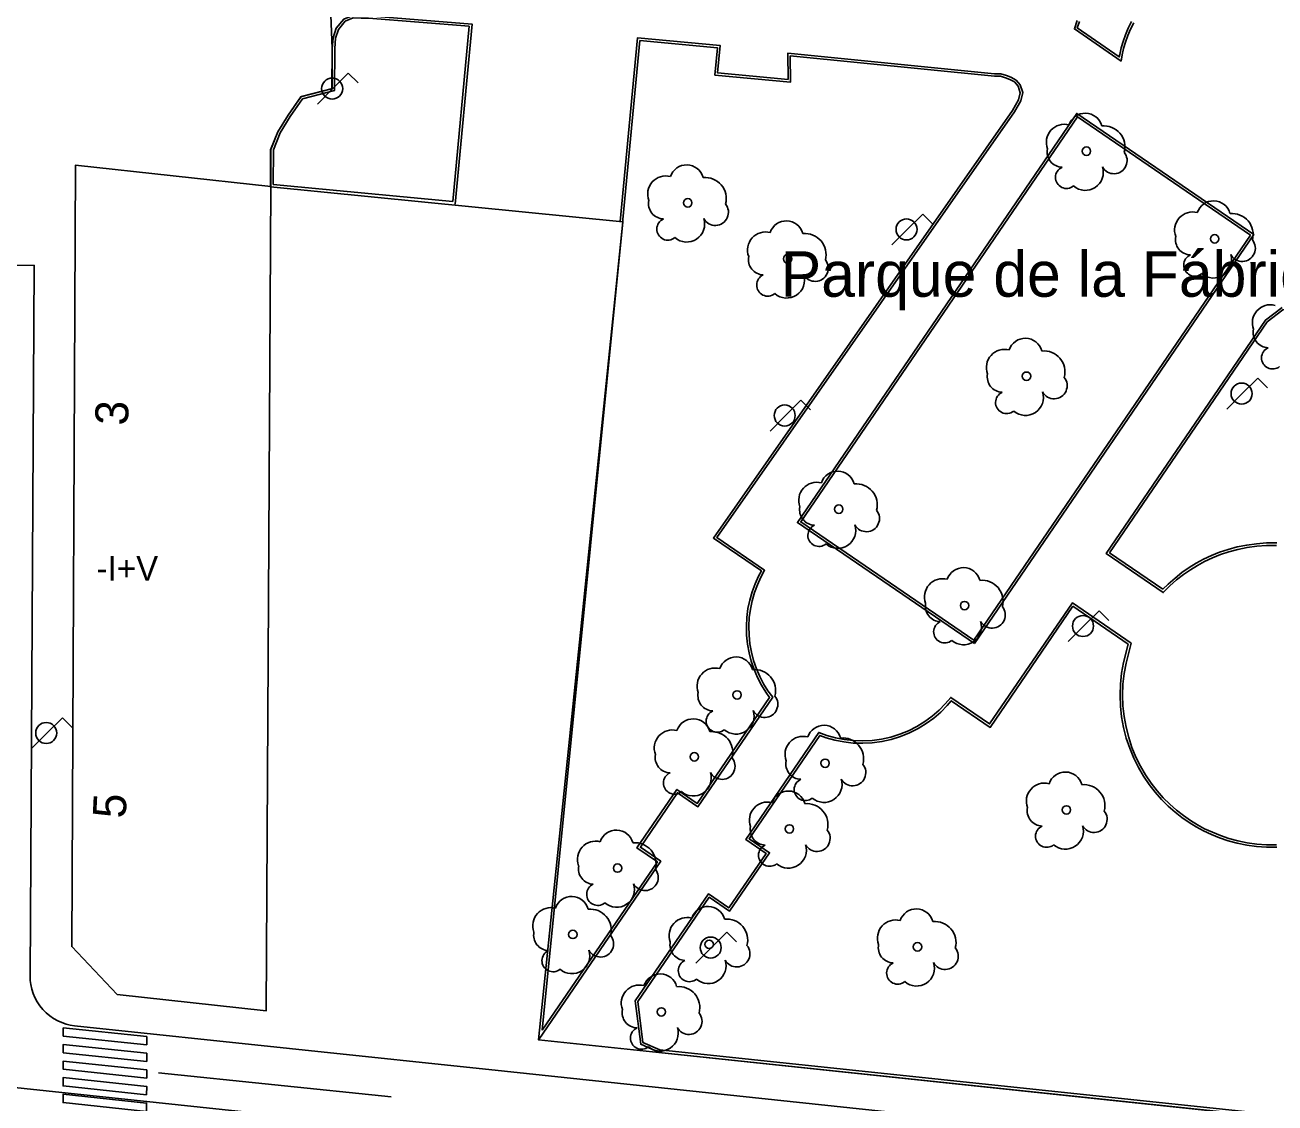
# Model space of a CAD drawing. Extents: x 282771 to 285132, y 4823109 to 4825496.
# Drawn here: x 282862 to 282937.8, y 4824029.5 to 4824094.8 of the extents above; entities that cross this region are included whole.
import ezdxf

# ---------------------------------------------------------------- set-up
doc = ezdxf.new("R2010")
doc.units = 0
for name, color, linetype in [('ACERA-BORDILLO', 7, 'Continuous'), ('ARBOL', 7, 'Continuous'), ('BORDILLO', 7, 'Continuous'), ('CALLE-EJE', 7, 'Continuous'), ('EDIFICIO', 7, 'Continuous'), ('FAROLA', 7, 'Continuous'), ('NUM-PORTAL', 7, 'Continuous'), ('PARQUE-JARDIN-AREA', 7, 'Continuous'), ('PARQUE-JARDIN-TEXTO', 7, 'Continuous'), ('PASO-PEATONES', 7, 'Continuous'), ('SENAL-VIARIA', 7, 'Continuous'), ('TXT-ALTURA-EDIFICIO', 7, 'Continuous'), ('ZONA-VERDE', 7, 'Continuous')]:
    doc.layers.add(name, color=color, linetype=linetype)

msp = doc.modelspace()

# ---------------------------------------------------------------- linework, layer by layer
at = {"layer": 'ACERA-BORDILLO'}
for points in [[(282988.023, 4824157.68), (282986.043, 4824139.146), (282981.145, 4824135.33), (282970.859, 4824041.966), (282974.673, 4824036.985), (282973.917, 4824027.481), (282973.629, 4824024.412), (282973.445, 4824023.861), (282973.196, 4824023.428), (282972.724, 4824023.074), (282972.2, 4824022.851), (282971.518, 4824022.891), (282891.09, 4824031.424)], [(282891.09, 4824031.424), (282865.031, 4824034.178), (282864.778, 4824034.216), (282864.522, 4824034.277), (282864.266, 4824034.363), (282864.014, 4824034.474), (282863.768, 4824034.61), (282863.534, 4824034.771), (282863.313, 4824034.956), (282863.111, 4824035.162), (282862.929, 4824035.386), (282862.77, 4824035.625), (282862.636, 4824035.876), (282862.527, 4824036.135), (282862.445, 4824036.399), (282862.388, 4824036.663), (282862.356, 4824036.924), (282862.346, 4824037.179), (282862.594, 4824080.223), (282861.132, 4824080.231), (282861.242, 4824099.318), (282862.704, 4824099.31)]]:
    msp.add_lwpolyline(points, dxfattribs=at)
at = {"layer": 'ARBOL'}
for centre in [(282926.33, 4824087.143), (282902.18, 4824084.013), (282934.1, 4824081.833), (282908.23, 4824080.623), (282922.7, 4824073.513), (282911.33, 4824065.463), (282918.95, 4824059.623), (282905.17, 4824054.213), (282902.58, 4824050.463), (282910.5, 4824050.073), (282925.12, 4824047.244), (282908.34, 4824046.094), (282897.93, 4824043.724), (282895.22, 4824039.704), (282903.48, 4824039.104), (282916.1, 4824038.954), (282900.58, 4824035.014)]:
    msp.add_circle(centre, 0.255, dxfattribs=at)
for centre, radius, start, end in [((282926.26, 4824088.403), 1.038, 15.64228, 161.38435), ((282925, 4824087.673), 1.097, 75.4318, 200.55608), ((282927.39, 4824087.403), 1.272, 345.03273, 95.79925), ((282924.89, 4824087.103), 0.935, 168.59898, 268.13236), ((282928, 4824086.573), 0.797, 208.96247, 38.99103), ((282900.85, 4824084.543), 1.097, 75.4318, 200.55608), ((282902.11, 4824085.273), 1.038, 15.64228, 161.38435), ((282925.13, 4824085.553), 0.672, 113.73672, 309.4725), ((282926.27, 4824085.853), 1.086, 228.95447, 17.92796), ((282903.24, 4824084.273), 1.272, 345.03273, 95.79925), ((282900.74, 4824083.973), 0.935, 168.59898, 268.13236), ((282934.03, 4824083.093), 1.038, 15.64228, 161.38435), ((282903.85, 4824083.443), 0.797, 208.96247, 38.99103), ((282932.77, 4824082.363), 1.097, 75.4318, 200.55608), ((282935.16, 4824082.093), 1.272, 345.03273, 95.79925), ((282900.98, 4824082.423), 0.672, 113.73672, 309.4725), ((282902.12, 4824082.723), 1.086, 228.95447, 17.92796), ((282908.16, 4824081.883), 1.038, 15.64228, 161.38435), ((282906.9, 4824081.153), 1.097, 75.4318, 200.55608), ((282909.29, 4824080.883), 1.272, 345.03273, 95.79925), ((282932.66, 4824081.793), 0.935, 168.59898, 268.13236), ((282935.77, 4824081.263), 0.797, 208.96247, 38.99103), ((282906.79, 4824080.583), 0.935, 168.59898, 268.13236), ((282909.9, 4824080.053), 0.797, 208.96247, 38.99103), ((282932.9, 4824080.243), 0.672, 113.73672, 309.4725), ((282934.04, 4824080.543), 1.086, 228.95447, 17.92796), ((282907.03, 4824079.033), 0.672, 113.73672, 309.4725), ((282908.17, 4824079.333), 1.086, 228.95447, 17.92796), ((282937.48, 4824076.743), 1.097, 75.4318, 200.55608), ((282922.63, 4824074.773), 1.038, 15.64228, 161.38435), ((282937.37, 4824076.173), 0.935, 168.59898, 268.13236), ((282921.37, 4824074.043), 1.097, 75.4318, 200.55608), ((282923.76, 4824073.773), 1.272, 345.03273, 95.79925), ((282937.61, 4824074.623), 0.672, 113.73672, 309.4725), ((282921.26, 4824073.473), 0.935, 168.59898, 268.13236), ((282924.37, 4824072.943), 0.797, 208.96247, 38.99103), ((282921.5, 4824071.923), 0.672, 113.73672, 309.4725), ((282922.64, 4824072.223), 1.086, 228.95447, 17.92796), ((282911.26, 4824066.723), 1.038, 15.64228, 161.38435), ((282910, 4824065.993), 1.097, 75.4318, 200.55608), ((282912.39, 4824065.723), 1.272, 345.03273, 95.79925), ((282909.89, 4824065.423), 0.935, 168.59898, 268.13236), ((282913, 4824064.893), 0.797, 208.96247, 38.99103), ((282910.13, 4824063.873), 0.672, 113.73672, 309.4725), ((282911.27, 4824064.173), 1.086, 228.95447, 17.92796), ((282918.88, 4824060.883), 1.038, 15.64228, 161.38435), ((282917.62, 4824060.153), 1.097, 75.4318, 200.55608), ((282920.01, 4824059.883), 1.272, 345.03273, 95.79925), ((282917.51, 4824059.583), 0.935, 168.59898, 268.13236), ((282920.62, 4824059.053), 0.797, 208.96247, 38.99103), ((282917.75, 4824058.033), 0.672, 113.73672, 309.4725), ((282918.89, 4824058.333), 1.086, 228.95447, 17.92796), ((282905.1, 4824055.473), 1.038, 15.64228, 161.38435), ((282903.84, 4824054.743), 1.097, 75.4318, 200.55608), ((282906.23, 4824054.473), 1.272, 345.03273, 95.79925), ((282903.73, 4824054.173), 0.935, 168.59898, 268.13236), ((282906.84, 4824053.643), 0.797, 208.96247, 38.99103), ((282903.97, 4824052.623), 0.672, 113.73672, 309.4725), ((282905.11, 4824052.923), 1.086, 228.95447, 17.92796), ((282902.51, 4824051.723), 1.038, 15.64228, 161.38435), ((282910.43, 4824051.333), 1.038, 15.64228, 161.38435), ((282901.25, 4824050.993), 1.097, 75.4318, 200.55608), ((282903.64, 4824050.723), 1.272, 345.03273, 95.79925), ((282909.17, 4824050.603), 1.097, 75.4318, 200.55608), ((282911.56, 4824050.333), 1.272, 345.03273, 95.79925), ((282901.14, 4824050.423), 0.935, 168.59898, 268.13236), ((282904.25, 4824049.893), 0.797, 208.96247, 38.99103), ((282909.06, 4824050.033), 0.935, 168.59898, 268.13236), ((282901.38, 4824048.873), 0.672, 113.73672, 309.4725), ((282902.52, 4824049.173), 1.086, 228.95447, 17.92796), ((282912.17, 4824049.503), 0.797, 208.96247, 38.99103), ((282925.05, 4824048.504), 1.038, 15.64228, 161.38435), ((282909.3, 4824048.484), 0.672, 113.73672, 309.4725), ((282910.44, 4824048.784), 1.086, 228.95447, 17.92796), ((282923.79, 4824047.774), 1.097, 75.4318, 200.55608), ((282926.18, 4824047.504), 1.272, 345.03273, 95.79925), ((282908.27, 4824047.354), 1.038, 15.64228, 161.38435), ((282907.01, 4824046.624), 1.097, 75.4318, 200.55608), ((282909.4, 4824046.354), 1.272, 345.03273, 95.79925), ((282923.68, 4824047.204), 0.935, 168.59898, 268.13236), ((282926.79, 4824046.674), 0.797, 208.96247, 38.99103), ((282906.9, 4824046.054), 0.935, 168.59898, 268.13236), ((282923.92, 4824045.654), 0.672, 113.73672, 309.4725), ((282925.06, 4824045.954), 1.086, 228.95447, 17.92796), ((282897.86, 4824044.984), 1.038, 15.64228, 161.38435), ((282910.01, 4824045.524), 0.797, 208.96247, 38.99103), ((282896.6, 4824044.254), 1.097, 75.4318, 200.55608), ((282898.99, 4824043.984), 1.272, 345.03273, 95.79925), ((282907.14, 4824044.504), 0.672, 113.73672, 309.4725), ((282908.28, 4824044.804), 1.086, 228.95447, 17.92796), ((282896.49, 4824043.684), 0.935, 168.59898, 268.13236), ((282899.6, 4824043.154), 0.797, 208.96247, 38.99103), ((282896.73, 4824042.134), 0.672, 113.73672, 309.4725), ((282897.87, 4824042.434), 1.086, 228.95447, 17.92796), ((282895.15, 4824040.964), 1.038, 15.64228, 161.38435), ((282893.89, 4824040.234), 1.097, 75.4318, 200.55608), ((282896.28, 4824039.964), 1.272, 345.03273, 95.79925), ((282903.41, 4824040.364), 1.038, 15.64228, 161.38435), ((282916.03, 4824040.214), 1.038, 15.64228, 161.38435), ((282902.15, 4824039.634), 1.097, 75.4318, 200.55608), ((282904.54, 4824039.364), 1.272, 345.03273, 95.79925), ((282914.77, 4824039.484), 1.097, 75.4318, 200.55608), ((282917.16, 4824039.214), 1.272, 345.03273, 95.79925), ((282893.78, 4824039.664), 0.935, 168.59898, 268.13236), ((282896.89, 4824039.134), 0.797, 208.96247, 38.99103), ((282894.02, 4824038.114), 0.672, 113.73672, 309.4725), ((282895.16, 4824038.414), 1.086, 228.95447, 17.92796), ((282902.04, 4824039.064), 0.935, 168.59898, 268.13236), ((282905.15, 4824038.534), 0.797, 208.96247, 38.99103), ((282914.66, 4824038.914), 0.935, 168.59898, 268.13236), ((282917.77, 4824038.384), 0.797, 208.96247, 38.99103), ((282902.28, 4824037.514), 0.672, 113.73672, 309.4725), ((282903.42, 4824037.814), 1.086, 228.95447, 17.92796), ((282914.9, 4824037.364), 0.672, 113.73672, 309.4725), ((282916.04, 4824037.664), 1.086, 228.95447, 17.92796), ((282900.51, 4824036.274), 1.038, 15.64228, 161.38435), ((282899.25, 4824035.544), 1.097, 75.4318, 200.55608), ((282901.64, 4824035.274), 1.272, 345.03273, 95.79925), ((282899.14, 4824034.974), 0.935, 168.59898, 268.13236), ((282902.25, 4824034.444), 0.797, 208.96247, 38.99103), ((282899.38, 4824033.424), 0.672, 113.73672, 309.4725), ((282900.52, 4824033.724), 1.086, 228.95447, 17.92796)]:
    msp.add_arc(centre, radius, start, end, dxfattribs=at)
at = {"layer": 'BORDILLO'}
for points in [[(282888.082, 4824083.938), (282889.113, 4824094.841), (282882.85, 4824095.343), (282882.408, 4824095.342), (282881.892, 4824095.369), (282881.341, 4824095.14), (282880.883, 4824094.589), (282880.699, 4824094.015), (282880.648, 4824093.367), (282880.64, 4824090.933), (282878.762, 4824090.447), (282877.969, 4824089.333), (282877.349, 4824088.323), (282876.93, 4824087.243), (282876.92, 4824084.993)], [(282929.195, 4824094.921), (282929.002, 4824094.531), (282928.837, 4824094.139), (282928.699, 4824093.747), (282928.586, 4824093.358), (282928.498, 4824092.975), (282928.433, 4824092.598), (282925.601, 4824094.546), (282925.766, 4824095.047)], [(282893.16, 4824033.334), (282900.55, 4824044.134), (282899.31, 4824044.984), (282901.56, 4824048.284), (282902.8, 4824047.434), (282907.327, 4824054.065), (282907.041, 4824054.459), (282906.78, 4824054.882), (282906.546, 4824055.329), (282906.343, 4824055.8), (282906.174, 4824056.29), (282906.042, 4824056.796), (282905.948, 4824057.314), (282905.895, 4824057.839), (282905.882, 4824058.367), (282905.91, 4824058.892), (282905.977, 4824059.411), (282906.083, 4824059.918), (282906.225, 4824060.411), (282906.4, 4824060.884), (282906.607, 4824061.336), (282906.84, 4824061.763), (282903.95, 4824063.743), (282921.978, 4824089.518), (282922.365, 4824090.193), (282922.483, 4824090.692), (282922.325, 4824091.151), (282922.076, 4824091.452), (282921.762, 4824091.623), (282921.486, 4824091.728), (282921.146, 4824091.833), (282920.762, 4824091.836), (282908.235, 4824093.075), (282908.258, 4824091.492), (282903.991, 4824091.882), (282904.151, 4824093.534), (282899.145, 4824094.013), (282898.092, 4824082.876)], [(282919.55, 4824057.323), (282908.82, 4824064.653), (282925.75, 4824089.433), (282936.48, 4824082.093), (282919.55, 4824057.323)], [(282938.181, 4824077.674), (282937.178, 4824076.911), (282927.524, 4824062.778), (282930.983, 4824060.413), (282931.386, 4824060.816), (282931.794, 4824061.176), (282932.21, 4824061.502), (282932.632, 4824061.795), (282933.057, 4824062.056), (282933.495, 4824062.294), (282933.96, 4824062.513), (282934.451, 4824062.71), (282934.966, 4824062.883), (282935.505, 4824063.028), (282936.066, 4824063.142), (282936.646, 4824063.222), (282937.243, 4824063.265), (282937.853, 4824063.268)], [(282929.042, 4824057.35), (282925.479, 4824059.786), (282920.47, 4824052.453), (282918.116, 4824054.062), (282917.779, 4824053.662), (282917.403, 4824053.281), (282916.99, 4824052.924), (282916.542, 4824052.595), (282916.063, 4824052.3), (282915.555, 4824052.043), (282915.024, 4824051.828), (282914.475, 4824051.657), (282913.913, 4824051.534), (282913.345, 4824051.458), (282912.777, 4824051.429), (282912.214, 4824051.448), (282911.662, 4824051.512), (282911.127, 4824051.618), (282910.611, 4824051.763), (282910.12, 4824051.943), (282905.69, 4824045.464), (282906.93, 4824044.614), (282904.67, 4824041.314), (282903.44, 4824042.164), (282899.006, 4824035.679), (282899.331, 4824033.054), (282900.447, 4824032.562), (282957.582, 4824026.536)], [(282937.853, 4824045.134), (282937.243, 4824045.137), (282936.646, 4824045.18), (282936.066, 4824045.26), (282935.505, 4824045.374), (282934.966, 4824045.519), (282934.451, 4824045.692), (282933.96, 4824045.889), (282933.495, 4824046.108), (282933.057, 4824046.346), (282932.632, 4824046.607), (282932.21, 4824046.9), (282931.794, 4824047.226), (282931.386, 4824047.586), (282930.991, 4824047.98), (282930.612, 4824048.409), (282930.252, 4824048.872), (282929.917, 4824049.367), (282929.61, 4824049.894), (282929.334, 4824050.449), (282929.093, 4824051.031), (282928.892, 4824051.636), (282928.732, 4824052.26), (282928.616, 4824052.899), (282928.545, 4824053.547), (282928.522, 4824054.201), (282928.545, 4824054.855), (282928.616, 4824055.503), (282928.732, 4824056.142), (282929.042, 4824057.35)]]:
    msp.add_lwpolyline(points, dxfattribs=at)
at = {"layer": 'CALLE-EJE'}
msp.add_lwpolyline([(282977.366, 4824018.14), (282859.299, 4824030.65)], dxfattribs=at)
at = {"layer": 'EDIFICIO'}
msp.add_lwpolyline([(282876.92, 4824084.993), (282876.641, 4824035.074), (282867.621, 4824036.064), (282864.861, 4824038.964), (282865.091, 4824086.293), (282876.92, 4824084.993)], dxfattribs=at)
at = {"layer": 'FAROLA'}
for p, q in [((282881.62, 4824091.863), (282880.68, 4824090.933)), ((282882.21, 4824091.273), (282881.62, 4824091.863)), ((282880.68, 4824090.933), (282879.75, 4824089.993)), ((282916.414, 4824083.333), (282915.474, 4824082.403)), ((282917.004, 4824082.743), (282916.414, 4824083.333)), ((282915.474, 4824082.403), (282914.544, 4824081.463)), ((282936.714, 4824073.391), (282935.774, 4824072.461)), ((282937.304, 4824072.801), (282936.714, 4824073.391)), ((282909.034, 4824072.063), (282908.094, 4824071.133)), ((282909.624, 4824071.473), (282909.034, 4824072.063)), ((282935.774, 4824072.461), (282934.844, 4824071.521)), ((282908.094, 4824071.133), (282907.165, 4824070.193)), ((282927.104, 4824059.313), (282926.164, 4824058.383)), ((282927.694, 4824058.723), (282927.104, 4824059.313)), ((282926.164, 4824058.383), (282925.234, 4824057.443)), ((282864.299, 4824052.833), (282863.359, 4824051.903)), ((282864.889, 4824052.243), (282864.299, 4824052.833)), ((282863.359, 4824051.903), (282862.429, 4824050.964)), ((282904.551, 4824039.84), (282903.611, 4824038.91)), ((282905.141, 4824039.25), (282904.551, 4824039.84)), ((282903.611, 4824038.91), (282902.681, 4824037.97))]:
    msp.add_line(p, q, dxfattribs=at)
for centre in [(282880.64, 4824090.933), (282915.434, 4824082.403), (282935.734, 4824072.461), (282908.054, 4824071.133), (282926.124, 4824058.383), (282863.319, 4824051.903), (282903.571, 4824038.91)]:
    msp.add_circle(centre, 0.637, dxfattribs=at)
at = {"layer": 'PARQUE-JARDIN-AREA'}
msp.add_lwpolyline([(282957.565, 4824026.52), (282900.429, 4824032.546), (282893.142, 4824033.318), (282898.242, 4824082.861), (282876.902, 4824084.978), (282876.912, 4824087.228), (282877.349, 4824088.323), (282877.969, 4824089.333), (282878.744, 4824090.432), (282880.622, 4824090.919), (282880.648, 4824093.367), (282880.369, 4824099.917), (282880.422, 4824101.837), (282917.293, 4824120.266), (282923.323, 4824123.277), (282968.997, 4824145.941)], dxfattribs=at)
at = {"layer": 'PASO-PEATONES'}
for points in [[(282869.41, 4824033.011), (282864.351, 4824033.546), (282864.352, 4824034.048), (282869.411, 4824033.514)], [(282869.407, 4824032.006), (282864.349, 4824032.54), (282864.35, 4824033.043), (282869.408, 4824032.509)], [(282869.405, 4824031.001), (282864.346, 4824031.535), (282864.348, 4824032.038), (282869.406, 4824031.503)], [(282869.402, 4824029.996), (282864.344, 4824030.53), (282864.345, 4824031.032), (282869.404, 4824030.498)], [(282869.4, 4824028.99), (282864.342, 4824029.524), (282864.343, 4824030.027), (282869.401, 4824029.493)]]:
    msp.add_lwpolyline(points, close=True, dxfattribs=at)
at = {"layer": 'SENAL-VIARIA'}
msp.add_lwpolyline([(282870.123, 4824031.314), (282884.225, 4824029.86)], dxfattribs=at)
at = {"layer": 'ZONA-VERDE'}
for p, q in [((282887.946, 4824084.101), (282888.949, 4824094.704)), ((282899.281, 4824093.849), (282898.255, 4824083.008)), ((282877.071, 4824085.13), (282887.946, 4824084.101)), ((282927.733, 4824062.817), (282930.965, 4824060.607)), ((282930.965, 4824060.607), (282931.283, 4824060.925)), ((282928.87, 4824057.286), (282925.518, 4824059.578))]:
    msp.add_line(p, q, dxfattribs=at)
for points in [[(282888.949, 4824094.704), (282882.845, 4824095.193), (282882.404, 4824095.192), (282881.918, 4824095.218), (282881.433, 4824095.015), (282881.017, 4824094.515), (282880.847, 4824093.986), (282880.798, 4824093.361), (282880.79, 4824090.817), (282878.852, 4824090.315), (282878.094, 4824089.25), (282877.484, 4824088.256), (282877.08, 4824087.215), (282877.071, 4824085.13)], [(282925.907, 4824094.996), (282925.779, 4824094.606), (282928.325, 4824092.854), (282928.351, 4824093.004), (282928.441, 4824093.396), (282928.556, 4824093.793), (282928.697, 4824094.193), (282928.866, 4824094.593), (282929.063, 4824094.992)], [(282893.368, 4824033.902), (282900.342, 4824044.095), (282899.102, 4824044.944), (282901.521, 4824048.492), (282902.761, 4824047.642), (282907.143, 4824054.062), (282906.916, 4824054.376), (282906.649, 4824054.807), (282906.41, 4824055.265), (282906.203, 4824055.746), (282906.03, 4824056.247), (282905.895, 4824056.764), (282905.8, 4824057.293), (282905.745, 4824057.83), (282905.732, 4824058.369), (282905.76, 4824058.906), (282905.829, 4824059.436), (282905.937, 4824059.954), (282906.082, 4824060.457), (282906.262, 4824060.941), (282906.472, 4824061.403), (282906.644, 4824061.716), (282903.74, 4824063.705), (282921.851, 4824089.598), (282922.224, 4824090.249), (282922.327, 4824090.684), (282922.192, 4824091.076), (282921.979, 4824091.334), (282921.699, 4824091.486), (282921.438, 4824091.586), (282921.122, 4824091.683), (282920.754, 4824091.686), (282908.388, 4824092.91), (282908.41, 4824091.327), (282903.827, 4824091.746), (282903.987, 4824093.399), (282899.281, 4824093.849)], [(282936.271, 4824082.054), (282925.789, 4824089.225), (282909.029, 4824064.693), (282919.511, 4824057.532), (282936.271, 4824082.054)], [(282898.255, 4824083.008), (282898.256, 4824083.008), (282898.242, 4824082.861), (282893.368, 4824033.902)], [(282945.243, 4824059.368), (282946.504, 4824059.987), (282947.471, 4824062.322), (282947.4, 4824062.491), (282944.881, 4824067.643), (282943.531, 4824066.983), (282941.639, 4824070.842), (282942.989, 4824071.502), (282940.504, 4824076.579), (282939.883, 4824077.28), (282939.197, 4824077.544), (282938.233, 4824077.525), (282937.288, 4824076.806), (282927.733, 4824062.817)], [(282931.283, 4824060.925), (282931.698, 4824061.291), (282932.121, 4824061.623), (282932.55, 4824061.921), (282932.982, 4824062.186), (282933.428, 4824062.427), (282933.9, 4824062.65), (282934.399, 4824062.851), (282934.923, 4824063.027), (282935.471, 4824063.174), (282936.041, 4824063.29), (282936.631, 4824063.371), (282937.237, 4824063.415), (282937.857, 4824063.418)], [(282925.518, 4824059.578), (282920.509, 4824052.245), (282918.143, 4824053.862), (282917.89, 4824053.561), (282917.506, 4824053.171), (282917.084, 4824052.806), (282916.626, 4824052.47), (282916.136, 4824052.169), (282915.617, 4824051.906), (282915.074, 4824051.687), (282914.513, 4824051.512), (282913.939, 4824051.386), (282913.359, 4824051.308), (282912.778, 4824051.279), (282912.203, 4824051.298), (282911.639, 4824051.364), (282911.092, 4824051.472), (282910.565, 4824051.62), (282910.178, 4824051.762), (282905.899, 4824045.503), (282907.139, 4824044.652), (282904.709, 4824041.105), (282903.479, 4824041.954), (282899.162, 4824035.642), (282899.47, 4824033.157), (282900.487, 4824032.709), (282957.555, 4824026.69)], [(282937.857, 4824044.984), (282937.237, 4824044.987), (282936.631, 4824045.031), (282936.041, 4824045.112), (282935.471, 4824045.228), (282934.923, 4824045.375), (282934.399, 4824045.551), (282933.9, 4824045.752), (282933.428, 4824045.975), (282932.982, 4824046.216), (282932.55, 4824046.481), (282932.121, 4824046.779), (282931.698, 4824047.111), (282931.283, 4824047.477), (282930.881, 4824047.878), (282930.496, 4824048.313), (282930.131, 4824048.784), (282929.79, 4824049.287), (282929.477, 4824049.822), (282929.197, 4824050.387), (282928.953, 4824050.979), (282928.748, 4824051.594), (282928.585, 4824052.228), (282928.467, 4824052.877), (282928.395, 4824053.536), (282928.371, 4824054.201), (282928.395, 4824054.866), (282928.467, 4824055.525), (282928.585, 4824056.174), (282928.87, 4824057.286)]]:
    msp.add_lwpolyline(points, dxfattribs=at)

# ---------------------------------------------------------------- texts
at = {"layer": 'NUM-PORTAL'}
for s, p in [('3', (282868.259, 4824070.501)), ('5', (282868.129, 4824046.705))]:
    msp.add_text(s, height=2, rotation=87.21004, dxfattribs=at).set_placement(p)
at = {"layer": 'PARQUE-JARDIN-TEXTO'}
msp.add_text('Parque de la Fábrica de Loza', height=2.75, dxfattribs=at).set_placement((282907.812, 4824078.327))
at = {"layer": 'TXT-ALTURA-EDIFICIO'}
msp.add_text('-I+V', height=1.5, rotation=0.00004, dxfattribs=at).set_placement((282866.369, 4824061.133))

doc.saveas('drawing.dxf')
